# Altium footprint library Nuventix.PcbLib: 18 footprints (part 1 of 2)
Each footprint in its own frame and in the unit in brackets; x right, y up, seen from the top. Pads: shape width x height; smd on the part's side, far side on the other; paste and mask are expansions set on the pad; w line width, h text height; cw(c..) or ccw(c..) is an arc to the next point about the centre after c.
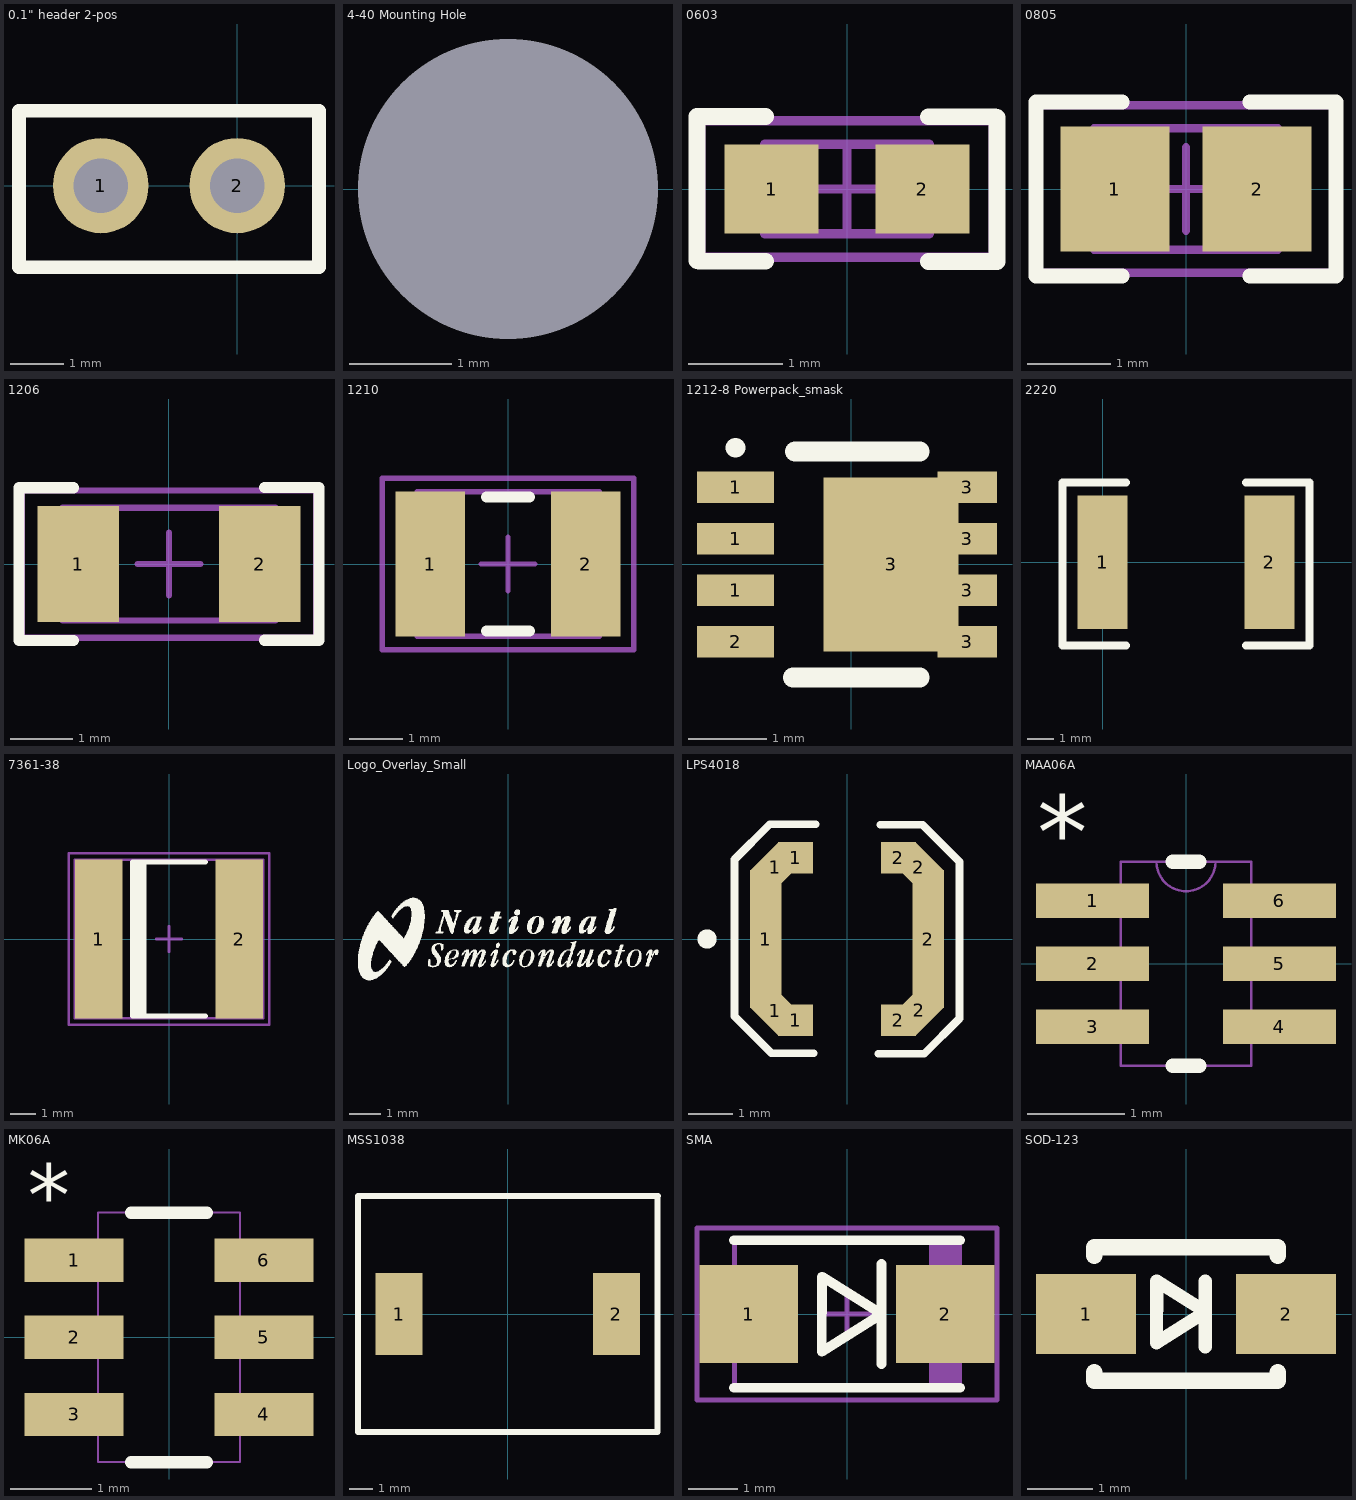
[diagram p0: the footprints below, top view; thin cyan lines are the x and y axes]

## 0.1" header 2-pos [mil] "standard 0.1\" headerstrip, two position"
pads (2):
  round 70 hole 40: 1(-100,0) 2(0,0)
Top Overlay:
  lines w10: -160,-60 60,-60 60,55 -160,55 -160,-60

## 4-40 Mounting Hole [mil] "Tooling Hole"
height 393.7
pads (1):
  round 0 hole 115 unplated: 0(175,0)

## 0603 [mm] "0603 from SM-752 data"
height 0.85
pads (2):
  rect 1x0.95 smd: 1(-0.8,0) 2(0.8,0)
Top Overlay:
  lines w0.178: -1.593,-0.762 -1.593,0.769 -0.864,0.769 ; -1.575,-0.767 -0.864,-0.767 ; 0.864,-0.769 1.593,-0.769 1.593,0.762 ; 0.864,0.767 1.575,0.767
Mechanical 13:
  lines w0.1: -0.875,-0.475 -0.875,0.475 0.875,0.475 0.875,-0.475 -0.875,-0.475
Mechanical 15:
  lines w0.1: -0.475,0 0.475,0 ; 0,-0.475 0,0.475 ; -1.55,-0.725 -1.55,0.725 1.55,0.725 1.55,-0.725 -1.55,-0.725
3D body: height 0.85, standoff 0, extent -0.875,-0.475 0.875,0.475

## 0805 [mm] "0805 from SM-752 data"
height 1.1
pads (2):
  rect 1.3x1.5 smd: 1(-0.85,0) 2(0.85,0)
Top Overlay:
  lines w0.178: -0.762,-1.041 -1.793,-1.041 -1.793,1.041 -0.762,1.041 ; 0.762,-1.041 1.793,-1.041 1.793,1.041 0.762,1.041
Mechanical 13:
  lines w0.1: -1.1,-0.725 1.1,-0.725 1.1,0.725 -1.1,0.725 -1.1,-0.725
Mechanical 15:
  lines w0.1: -0.5,0 0.5,0 ; 0,-0.5 0,0.5 ; -1.775,-1 1.775,-1 1.775,1 -1.775,1 -1.775,-1
3D body: height 1.1, standoff 0, extent -1.1,-0.725 1.1,0.725

## 1206 [mm] "1206 from SM-752 data"
height 1.35
pads (2):
  rect 1.3x1.85 smd: 1(-1.45,0) 2(1.45,0)
Top Overlay:
  lines w0.178: -1.525,1.218 -2.393,1.218 -2.393,-1.215 -2.391,-1.217 -1.523,-1.217 ; 1.524,1.219 2.392,1.219 2.394,1.217 2.394,-1.216 1.526,-1.216
Mechanical 13:
  lines w0.1: -1.7,-0.9 1.7,-0.9 1.7,0.9 -1.7,0.9 -1.7,-0.9
Mechanical 15:
  lines w0.1: -0.5,0 0.5,0 ; 0,-0.5 0,0.5 ; -2.35,-1.175 2.35,-1.175 2.35,1.175 -2.35,1.175 -2.35,-1.175
3D body: height 1.35, standoff 0, extent -1.7,-0.9 1.7,0.9

## 1210 [mm] "1210 from SM-752 data"
height 1.35
pads (2):
  rect 1.3x2.7 smd: 1(-1.45,0) 2(1.45,0)
Top Overlay:
  lines w0.2: -0.4,-1.25 0.4,-1.25 ; -0.4,1.25 0.4,1.25
Mechanical 13:
  lines w0.1: -1.7,-1.35 -1.7,1.35 1.7,1.35 1.7,-1.35 -1.7,-1.35
Mechanical 15:
  lines w0.1: -0.5,0 0.5,0 ; 0,-0.5 0,0.5 ; -2.35,-1.6 -2.35,1.6 2.35,1.6 2.35,-1.6 -2.35,-1.6
3D body: height 1.35, standoff 0, extent -1.7,-1.35 1.7,1.35

## 1212-8 Powerpack_smask [mil]
pads (9):
  rect 39x16 smd: 1(-58.5,-13) 1(-58.5,13) 1(-58.5,39) 2(-58.5,-39)
  rect 68x88 smd: 3(20,0)
  rect 30x16 smd: 3(58.5,-39) 3(58.5,-13) 3(58.5,13) 3(58.5,39)
Top Overlay:
  lines w10: -58.53,59 -58.5,59 ; -29.5,-57 34.5,-57 ; -28.5,57 34.5,57

## 2220 [mil]
pads (2):
  rect 75x200 smd: 1(0,0) 2(250,0)
Top Overlay:
  lines w12: 35,-125 -60,-125 -60,120 35,120 ; 215,-125 310,-125 310,120 215,120

## 7361-38 [mm] "Medium density IPC based on AVX dimensions for TPS series"
height 3.8
pads (2):
  rect 1.9x6.35 smd: 1(-2.8,0) 2(2.8,0)
Top Overlay:
  rectangle: -1.45,-3.075 -0.9,3.075
  lines w0.2: 1.45,-3.075 -1.45,-3.075 -1.45,3.075 1.45,3.075
Mechanical 13:
  lines w0.1: -3.75,-3.15 3.75,-3.15 3.75,3.15 -3.75,3.15 -3.75,-3.15
Mechanical 15:
  lines w0.1: -0.5,0 0.5,0 ; 0,-0.5 0,0.5 ; -4,-3.425 4,-3.425 4,3.425 -4,3.425 -4,-3.425
3D body: height 3.8, standoff 0, extent -3.75,-3.15 3.75,3.15

## Logo_Overlay_Small [mil]
Top Overlay:
  drawing of 24 lines, arcs and shapes, not listed

## LPS4018 [mil]
height 71
pads (10):
  rect 28x123 smd: 1(-72.5,0) 2(72.5,0)
  rect 35.5x28 smd rot 135: 1(-64,-64) 2(64,64)
  rect 35.5x28 smd rot 45: 1(-64,64) 2(64.5,-63.5)
  rect 31.5x28 smd: 1(-46,-72.5) 1(-46,72.5) 2(46,-72.5) 2(46,72.5)
Top Overlay:
  circle w10: c-125,0 r3.54
  lines w7: -30,-102 -67.5,-102 -100.5,-69 -100.5,71 -69,102.5 -28,102.5 ; 28,-102.5 69,-102.5 100.5,-71 100.5,69 67.5,102 30,102

## MAA06A [mil]
pads (6):
  rect 46x14 smd: 1(-38,25.59) 2(-38,0) 3(-38,-25.59) 4(38,-25.59) 5(38,0) 6(38,25.59)
Top Overlay:
  lines w6: -5.4,-41.5 5.4,-41.5 ; -5.4,41.5 5.4,41.5
  text "*" at -60.52,38.74 h30
Mechanical 1:
  lines w1: -12,41.5 ccw(c0,41.5) 12,41.5 ; -47,-31.59 -26.5,-31.59 -26.5,-19.59 -47,-19.59 -47,-31.59 ; -47,-6 -26.5,-6 -26.5,6 -47,6 -47,-6 ; -47,19.59 -26.5,19.59 -26.5,31.59 -47,31.59 -47,19.59 ; -26.5,-41.5 26.5,-41.5 26.5,41.5 -26.5,41.5 -26.5,-41.5 ; 26.5,-31.59 47,-31.59 47,-19.59 26.5,-19.59 26.5,-31.59 ; 26.5,-6 47,-6 47,6 26.5,6 26.5,-6 ; 26.5,19.59 47,19.59 47,31.59 26.5,31.59 26.5,19.59
  text "*" at -60.52,38.74 h40

## MK06A [mil]
pads (6):
  rect 48x21 smd: 1(-46,37.4) 2(-46,0) 3(-46,-37.4) 4(46,-37.4) 5(46,0) 6(46,37.4)
Top Overlay:
  lines w6: -18.41,-60.5 18.41,-60.5 ; -18.41,60.5 18.41,60.5
  text "*" at -68.52,54.05 h30
Mechanical 1:
  lines w1: -56,-46.9 -56,-27.9 -34.5,-27.9 -34.5,-46.9 -56,-46.9 ; -56,-9.5 -56,9.5 -34.5,9.5 -34.5,-9.5 -56,-9.5 ; -56,27.9 -56,46.9 -34.5,46.9 -34.5,27.9 -56,27.9 ; -34.5,-60.5 34.5,-60.5 34.5,60.5 -34.5,60.5 -34.5,-60.5 ; 34.5,-46.9 34.5,-27.9 56,-27.9 56,-46.9 34.5,-46.9 ; 34.5,-9.5 34.5,9.5 56,9.5 56,-9.5 34.5,-9.5 ; 34.5,27.9 34.5,46.9 56,46.9 56,27.9 34.5,27.9
  text "*" at -68.52,54.05 h40

## MSS1038 [mil]
pads (2):
  rect 80x140 smd: 1(-185,0) 2(185,0)
Top Overlay:
  lines w10: -255,201 -255,0 -255,-201 255,-201 255,201 ; -254,201 256,201

## SMA [mm] "Molded Diode, 2-Leads, Body 4.3x2.6mm, IPC Medium Density, based on OnSemi component dimensions and land pattern"
height 2.27
pads (2):
  rect 2x2 smd: 1(-2,0) 2(2,0)
Top Overlay:
  lines w0.2: -2.3,-1.5 2.3,-1.5 ; -2.3,1.5 2.3,1.5 ; 0.698,-0.004 -0.512,-0.766 -0.507,0.758 0.698,0.006
  lines w0.203: 0.698,-1.022 0.698,1.016
Mechanical 13:
  rectangle: 1.67,-1.46 2.285,1.46
  lines w0.1: -2.285,-1.46 -2.285,1.46 2.285,1.46 2.285,-1.46 -2.285,-1.46
Mechanical 15:
  lines w0.1: -0.5,0 0.5,0 ; 0,-0.5 0,0.5 ; -3.05,-1.75 -3.05,1.75 3.05,1.75 3.05,-1.75 -3.05,-1.75
3D body: height 2.27, standoff 0, extent -2.285,-1.46 2.285,1.46

## SOD-123 [mil]
pads (2):
  rect 60x48 smd: 1(-60,0) 2(60,0)
Top Overlay:
  lines w7.87: 11.59,1.17 -17.67,-17.26 -17.55,19.74 11.59,1.55
  lines w8: 11.59,-19.68 11.59,19.68
  lines w10: -55,-35 -55,-40 55,-40 55,-35 ; -55,35 -55,40 55,40 55,35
